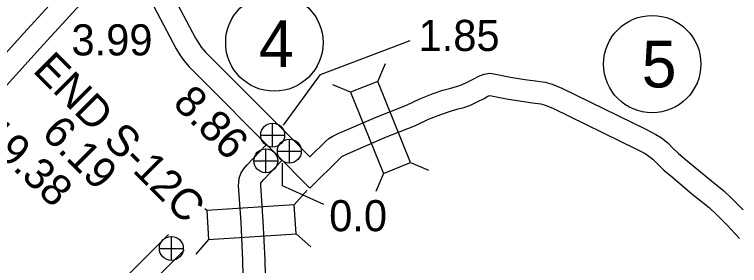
# Model space of a CAD drawing. Extents: x -939622 to -934222, y 1383701 to 1385301.
# Drawn here: x -936314.72 to -936285.22, y 1384531.32 to 1384541.55 of the extents above; entities that cross this region are included whole.
import ezdxf

# ---------------------------------------------------------------- set-up
doc = ezdxf.new("R2010")
doc.units = 0
for name, color, linetype in [('10', 7, 'Continuous'), ('20', 7, 'Continuous'), ('25', 7, 'Continuous'), ('26', 7, 'Continuous'), ('27', 7, 'Continuous')]:
    doc.layers.add(name, color=color, linetype=linetype)

msp = doc.modelspace()

# ---------------------------------------------------------------- linework, layer by layer
at = {"layer": '10'}
for points in [[(-936310.663, 1384546.215), (-936310.505, 1384546.14), (-936310.363, 1384546.052), (-936310.167, 1384545.848), (-936310.064, 1384545.684), (-936309.933, 1384545.459), (-936309.158, 1384544.007), (-936307.35, 1384540.58), (-936307.239, 1384540.389), (-936307.12, 1384540.221), (-936306.944, 1384540.014), (-936306.691, 1384539.753), (-936303.521, 1384536.57)], [(-936327.261, 1384531.367), (-936327.163, 1384531.037), (-936327.081, 1384530.743), (-936327.072, 1384530.722), (-936327.065, 1384530.711), (-936327.031, 1384530.676), (-936326.038, 1384529.807), (-936325.036, 1384528.926), (-936322.912, 1384531.297), (-936317.45, 1384537.347), (-936314.339, 1384540.779), (-936312.11, 1384543.231), (-936311.955, 1384543.388), (-936311.874, 1384543.497), (-936311.741, 1384543.699), (-936310.85, 1384545.233)], [(-936311.111, 1384545.404), (-936310.893, 1384545.304), (-936310.879, 1384545.29), (-936310.833, 1384545.218), (-936310.72, 1384545.021), (-936309.953, 1384543.586), (-936308.137, 1384540.144), (-936307.997, 1384539.902), (-936307.831, 1384539.668), (-936307.611, 1384539.409), (-936307.334, 1384539.123), (-936304.159, 1384535.935)], [(-936327.938, 1384530.458), (-936327.871, 1384530.302), (-936327.777, 1384530.153), (-936327.651, 1384530.023), (-936326.632, 1384529.13), (-936324.96, 1384527.662), (-936322.243, 1384530.695), (-936316.783, 1384536.743), (-936313.672, 1384540.174), (-936311.456, 1384542.612), (-936311.271, 1384542.8), (-936311.137, 1384542.979), (-936310.975, 1384543.224), (-936310.353, 1384544.297)], [(-936303.521, 1384536.57), (-936302.703, 1384535.746), (-936302.071, 1384536.372), (-936301.933, 1384536.499), (-936301.765, 1384536.591), (-936301.547, 1384536.695), (-936300.001, 1384537.36), (-936298.767, 1384537.857), (-936298.226, 1384538.108), (-936297.685, 1384538.321), (-936297.297, 1384538.458), (-936296.963, 1384538.551), (-936296.701, 1384538.623), (-936296.54, 1384538.678), (-936296.28, 1384538.803), (-936296.032, 1384538.92), (-936295.833, 1384539.036), (-936295.607, 1384539.113), (-936295.38, 1384539.154), (-936295.15, 1384539.113), (-936294.547, 1384538.998), (-936293.953, 1384538.9), (-936293.525, 1384538.837), (-936293.137, 1384538.788), (-936292.848, 1384538.709), (-936292.448, 1384538.548), (-936289.032, 1384536.872), (-936288.623, 1384536.661), (-936288.396, 1384536.52), (-936288.144, 1384536.323), (-936287.943, 1384536.108), (-936287.699, 1384535.881), (-936287.358, 1384535.587), (-936286.586, 1384534.94), (-936285.862, 1384534.356), (-936285.526, 1384534.038), (-936285.08, 1384533.582)], [(-936304.16, 1384535.936), (-936302.707, 1384534.473), (-936301.45, 1384535.721), (-936301.406, 1384535.761), (-936301.355, 1384535.789), (-936301.175, 1384535.875), (-936299.655, 1384536.529), (-936298.41, 1384537.03), (-936297.871, 1384537.28), (-936297.37, 1384537.477), (-936297.026, 1384537.599), (-936296.722, 1384537.683), (-936296.436, 1384537.763), (-936296.198, 1384537.844), (-936295.894, 1384537.991), (-936295.614, 1384538.122), (-936295.457, 1384538.213), (-936295.38, 1384538.239), (-936295.379, 1384538.239), (-936295.314, 1384538.228), (-936294.704, 1384538.112), (-936294.093, 1384538.011), (-936293.647, 1384537.945), (-936293.313, 1384537.903), (-936293.136, 1384537.854), (-936292.814, 1384537.725), (-936289.437, 1384536.068), (-936289.068, 1384535.877), (-936288.911, 1384535.781), (-936288.753, 1384535.656), (-936288.578, 1384535.471), (-936288.3, 1384535.211), (-936287.941, 1384534.902), (-936287.157, 1384534.245), (-936286.454, 1384533.678), (-936286.157, 1384533.397), (-936285.729, 1384532.959), (-936285.225, 1384532.424)], [(-936305.252, 1384523.524), (-936305.425, 1384531.525), (-936305.504, 1384533.081), (-936305.601, 1384534.562), (-936305.597, 1384534.699), (-936305.585, 1384534.875), (-936305.513, 1384535.071), (-936305.406, 1384535.242), (-936305.254, 1384535.425), (-936304.48, 1384536.235)], [(-936304.352, 1384523.544), (-936304.525, 1384531.558), (-936304.606, 1384533.133), (-936304.7, 1384534.577), (-936304.697, 1384534.657), (-936304.696, 1384534.68), (-936304.674, 1384534.715), (-936304.582, 1384534.826), (-936303.853, 1384535.588)], [(-936322.929, 1384518.137), (-936321.148, 1384519.884), (-936317.301, 1384523.693), (-936312.798, 1384528.225), (-936308.458, 1384532.586)], [(-936322.321, 1384517.473), (-936320.517, 1384519.243), (-936316.665, 1384523.056), (-936312.16, 1384527.591), (-936307.82, 1384531.951)]]:
    msp.add_lwpolyline(points, dxfattribs=at)
at = {"layer": '20'}
for p, q in [((-936299.943, 1384538.819), (-936299.632, 1384539.548)), ((-936301.045, 1384538.376), (-936301.773, 1384538.686)), ((-936298.612, 1384535.513), (-936297.883, 1384535.203)), ((-936299.714, 1384535.07), (-936300.024, 1384534.341)), ((-936303.341, 1384533.793), (-936302.819, 1384534.388)), ((-936303.341, 1384533.793), (-936306.898, 1384533.561)), ((-936303.264, 1384532.607), (-936303.341, 1384533.793)), ((-936306.898, 1384533.561), (-936306.975, 1384533.628)), ((-936306.898, 1384533.561), (-936306.821, 1384532.375)), ((-936306.821, 1384532.375), (-936303.264, 1384532.607)), ((-936303.264, 1384532.607), (-936302.669, 1384532.085)), ((-936306.821, 1384532.375), (-936307.343, 1384531.78))]:
    msp.add_line(p, q, dxfattribs=at)
msp.add_lwpolyline([(-936298.612, 1384535.513), (-936299.943, 1384538.819), (-936301.045, 1384538.376), (-936299.714, 1384535.07)], close=True, dxfattribs=at)
at = {"layer": '25'}
for p, q in [((-936303.816, 1384534.568), (-936303.816, 1384535.487)), ((-936302.139, 1384533.811), (-936303.816, 1384534.568)), ((-936306.898, 1384533.561), (-936306.975, 1384533.628))]:
    msp.add_line(p, q, dxfattribs=at)
msp.add_lwpolyline([(-936303.779, 1384537.043), (-936302.276, 1384539.103), (-936298.622, 1384540.486)], dxfattribs=at)
at = {"layer": '26'}
for p, q in [((-936304.218, 1384536.146), (-936304.218, 1384537.121)), ((-936304.705, 1384536.634), (-936303.73, 1384536.634)), ((-936303.538, 1384535.495), (-936303.538, 1384536.47)), ((-936304.499, 1384535.101), (-936304.499, 1384536.076)), ((-936304.026, 1384535.982), (-936303.051, 1384535.982)), ((-936304.986, 1384535.588), (-936304.011, 1384535.588)), ((-936308.339, 1384531.53), (-936308.339, 1384532.505)), ((-936308.827, 1384532.018), (-936307.852, 1384532.018))]:
    msp.add_line(p, q, dxfattribs=at)
for centre in [(-936304.218, 1384536.634), (-936303.538, 1384535.982), (-936304.499, 1384535.588), (-936308.339, 1384532.018)]:
    msp.add_circle(centre, 0.487, dxfattribs=at)
at = {"layer": '27'}
for centre in [(-936304.149, 1384540.399), (-936288.776, 1384539.525)]:
    msp.add_circle(centre, 1.98, dxfattribs=at)

# ---------------------------------------------------------------- texts
at = {"layer": '25'}
for s, p in [('3.99', (-936312.403, 1384539.878)), ('1.85', (-936298.282, 1384540.059)), ('0.0', (-936301.918, 1384532.717))]:
    msp.add_text(s, height=1.2672, dxfattribs=at).set_placement(p)
for s, rotation, p in [('END S-12C', 315, (-936314.019, 1384539.228)), ('8.86', 315, (-936308.325, 1384537.884)), ('6.19', 315, (-936313.664, 1384536.655)), ('19.38', 316.4326, (-936316.191, 1384536.551))]:
    msp.add_text(s, height=1.2672, rotation=rotation, dxfattribs=at).set_placement(p)
at = {"layer": '27'}
for s, p in [('4', (-936304.771, 1384539.402)), ('5', (-936289.201, 1384538.574))]:
    msp.add_text(s, height=1.901, dxfattribs=at).set_placement(p)

doc.saveas('drawing.dxf')
